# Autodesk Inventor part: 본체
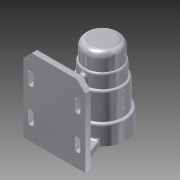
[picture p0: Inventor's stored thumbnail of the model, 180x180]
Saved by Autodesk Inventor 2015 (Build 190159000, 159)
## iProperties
Created: 2017-09
Part Number: 본체
Material: 알루미늄 6061
Document SubType Name: Modeling
Designer: Administrator
Density: 2.7 g/cm^3
Appearance: 알루미늄 - 평지
Mass: 695.321 g
Surface Area: 712.363 cm^2
Volume: 257.526 cm^3
Author: Administrator
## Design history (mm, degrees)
sketch "스케치1"
  geometry: L1 (-45, -56)-(45, -56); L2 (45, -56)-(45, 56); L3 (45, 56)-(-45, 56); L4 (-45, 56)-(-45, -56); L5 (-45, -56)-(45, 56); L6 (45, -56)-(-45, 56); 1 further point
  constraints: 12 end point, 2 midpoint, 2 parallel, 1 horizontal, 1 perpendicular
  dimensions: "d0" = 90 distance of L3.end L2.end; "d1" = 112 distance of L2.end L1.end
extrude "돌출1" new body sketch "스케치1" distance "d2" = 8; taper "d3" = 0 deg
sketch "스케치2"
  geometry: 1 further point
sketch "스케치3"
  geometry: L1 (0, -56)-(-8, -56) reference; L2 (-8, -56)-(-8, 56) reference; L3 (-8, 56)-(0, 56) reference; L4 (0, 56)-(0, -56) reference; L5 (62, -56)-(83, -56); L6 (83, -56)-(83, -41); L7 (83, -41)-(86, -41); L8 (86, -41)-(86, 13); L9 (86, 13)-(83, 13); L10 (83, 13)-(83, 25); L11 (83, 25)-(79, 25); L12 (79, 25)-(79, 43); L13 (79, 43)-(78, 43); L14 (78, 43)-(78, 47); L15 (78, 47)-(72.5, 47); L16 (72.5, 47)-(72.5, 50); L17 (72.5, 50)-(62, 50); L18 (83, -56)-(117.075, -56); L19 (62, 139.479)-(62, -56.834); L20 (62, 56)-(87, 56); L21 (87, 56)-(87, 31); L22 (87, 31)-(89, 31); L23 (89, 31)-(89, 11); L24 (89, 11)-(92, 11); L25 (92, 11)-(92, -28); L26 (92, -28)-(96, -28); L27 (83, -56)-(96, -56); L28 (96, -56)-(96, -28); 1 further point
  constraints: 48 end point, 18 perpendicular, 6 point on line, 2 horizontal, 2 vertical
  dimensions: "d4" = 70 distance from line of L2 L5.start; "d5" = 15 distance of L5.end L6.end; "d6" = 54 distance between parallel lines of L9 L7; "d7" = 12 distance between parallel lines of L11 L9; "d8" = 18 distance between parallel lines of L13 L11; "d9" = 4 distance of L13.end L14.end; "d10" = 3 distance of L15.end L16.end; "d11" = 42 diameter of L6 L19; "d12" = 21 diameter of L16 L19; "d13" = 32 diameter of L14 L19; "d14" = 34 diameter of L12 L19; "d15" = 42 diameter of L10 L19 (derived); "d16" = 48 diameter of L8 L19; "d17" = 112 distance between parallel lines of L20 L27; "d18" = 50 diameter of L21 L19; "d19" = 54 diameter of L23 L19; "d20" = 60 diameter of L25 L19; "d21" = 25 distance of L20.end L21.end; "d22" = 45 distance from line of L20 L24.end; "d23" = 84 distance between parallel lines of L26 L20; "d24" = 68 diameter of L28 L19
revolve "회전1" sketch "스케치3" stored, may be unused: angle "d25" = 90 deg
sketch "스케치4"
  geometry: L1 (0, -8)-(0, 0) reference; L2 (0, 0)-(90, 0) reference; L3 (90, 0)-(90, -8) reference; L4 (90, -8)-(0, -8) reference; L5 (90, 0)-(80, 0); L6 (0, 0)-(90, 0) reference; L7 (80, 0)-(66.9, 35.992); L8 (0, 0)-(10, 0); L9 (10, 0)-(23.1, 35.992); C1 r 21 at (45, 62) reference; A1 r 34 centre (45, 62) between (66.9, 35.992) and (23.1, 35.992) reference; 1 further point
  constraints: 8 end point, 2 point on circle, 2 point on line
  dimensions: "d26" = 10 distance of L2.end L5.end; "d27" = 110 deg angle of L5 L7; "d28" = 10 distance of L1.end L8.end
extrude "돌출2" join sketch "스케치4" distance "d30" = 8; taper "d31" = 0 deg
sketch "스케치5"
  geometry: L1 (-8, 56)-(0, 56) reference; L2 (0, 56)-(0, -48) reference; L3 (0, -48)-(28, -48) reference; L4 (28, -48)-(28, -28) reference; L5 (28, -28)-(32, -28) reference; L6 (32, -28)-(32, 11) reference; L7 (32, 11)-(35, 11) reference; L8 (35, 11)-(35, 31) reference; L9 (35, 31)-(37, 31) reference; L10 (37, 31)-(37, 56) reference; L11 (37, 56)-(87, 56) reference; L12 (87, 56)-(87, 31) reference; L13 (87, 31)-(89, 31) reference; L14 (89, 31)-(89, 11) reference; L15 (89, 11)-(92, 11) reference; L16 (92, 11)-(92, -28) reference; L17 (92, -28)-(96, -28) reference; L18 (96, -28)-(96, -56) reference; L19 (96, -56)-(83, -56) reference; L20 (83, -56)-(83, -41) reference; L21 (83, -41)-(86, -41) reference; L22 (86, -41)-(86, 13) reference; L23 (86, 13)-(83, 13) reference; L24 (83, 13)-(83, 25) reference; L25 (83, 25)-(79, 25) reference; L26 (79, 25)-(79, 43) reference; L27 (79, 43)-(78, 43) reference; L28 (78, 43)-(78, 47) reference; L29 (78, 47)-(72.5, 47) reference; L30 (72.5, 47)-(72.5, 50) reference; L31 (72.5, 50)-(51.5, 50) reference; L32 (51.5, 50)-(51.5, 47) reference; L33 (51.5, 47)-(46, 47) reference; L34 (46, 47)-(46, 43) reference; L35 (46, 43)-(45, 43) reference; L36 (45, 43)-(45, 25) reference; L37 (45, 25)-(41, 25) reference; L38 (41, 25)-(41, 13) reference; L39 (41, 13)-(38, 13) reference; L40 (38, 13)-(38, -41) reference; L41 (38, -41)-(41, -41) reference; L42 (41, -41)-(41, -56) reference; L43 (41, -56)-(-8, -56) reference; L44 (-8, -56)-(-8, 56) reference; L45 (0, 56)-(0, 34); L46 (0, -56)-(0, 56) reference; L47 (0, 34)-(38, 23.818); L48 (0, 34)-(39.34, 34); L49 (-8, 56)-(0, 56) reference; L50 (0, 56)-(0, -48) reference; L51 (0, -48)-(28, -48) reference; L52 (28, -48)-(28, -28) reference; L53 (28, -28)-(32, -28) reference; L54 (32, -28)-(32, 11) reference; L55 (32, 11)-(35, 11) reference; L56 (35, 11)-(35, 31) reference; L57 (35, 31)-(37, 31) reference; L58 (37, 31)-(37, 56) reference; L59 (37, 56)-(87, 56) reference; L60 (87, 56)-(87, 31) reference; L61 (87, 31)-(89, 31) reference; L62 (89, 31)-(89, 11) reference; L63 (89, 11)-(92, 11) reference; L64 (92, 11)-(92, -28) reference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; 1 further point
  constraints: 10 end point, 1 equal length, 1 horizontal, 1 midpoint, 1 point on line, 1 vertical
  dimensions: "d32" = 22 distance of L1.end L45.end; "d72" = 15 deg angle of L47 L48
  node "절단 모서리 투영3"
  node "절단 모서리 투영7"
  node "절단 모서리 투영8"
sketch "스케치6"
  geometry: L1 (-45, -56)-(-45, 56) reference; L2 (-45, 56)-(-35, 56) reference; L3 (-35, 48)-(-35, 56) reference; L4 (35, 48)-(-35, 48) reference; L5 (35, 56)-(35, 48) reference; L6 (35, 56)-(45, 56) reference; L7 (45, 56)-(45, -56) reference; L8 (45, -56)-(-45, -56) reference; L9 (-35, 56)-(35, 56) reference; L10 (-45, 56)-(-45, 34.95); L11 (-45, -56)-(-45, 56) reference; L12 (45, -56)-(-45, -56) reference; L13 (0, -56)-(-34, -56); L14 (-45, 22.956)-(-45, -17.044); L15 (-45, -17.044)-(-38, -17.044); L16 (-45, 56)-(-45, -56) reference; L17 (-34, 22.956)-(-34, -39.008); L18 (-30, -17.044)-(-30, -29.044); L19 (-38, -17.044)-(-38, -29.044); L20 (-30, -17.044)-(-30, -29.044); L21 (-38, -29.036)-(-37.974, -16.593); L22 (-45, 56)-(-45, 32); L23 (-45, 32)-(-34, 32); L24 (-34, 32)-(-34, 28.056); L25 (-34, 32)-(-34, 20); L26 (-30, 32)-(-30, 20); L27 (-38, 32)-(-38, 20); L28 (0, 28.056)-(-30, 28.056); L29 (-33.331, 28.056)-(-34, 28.056); C1 r 4 at (-34, -29.044); A1 r 4 centre (-34, -29.044) between (-38, -29.036) and (-30, -29.044); A2 r 4 centre (-34, -17.044) between (-30, -17.044) and (-38, -17.044); A3 r 4 centre (-34, 20) between (-38, 20) and (-30, 20); A4 r 4 centre (-34, 32) between (-34, 28) and (-33.331, 28.056); A5 r 4 centre (-34, 32) between (-30, 32) and (-38, 32); 2 further points
  constraints: 34 end point, 11 point on circle, 10 point on line, 6 centre point, 6 tangent, 4 coincident, 4 vertical, 3 horizontal, 2 perpendicular, 1 midpoint, 1 parallel, 3 other
  dimensions: "d36" = 34 distance of L13.start L13.end; "d44" = 40 distance of L14.start L14.end; "d49" = 12 distance of L18.start L18.end; "d50" = 12 distance of L15.end L19.end; "d87" = 24 distance of L1.end L22.end; "d88" = 34 distance of L28.start L24.end; "d90" = 12 distance of L25.start L25.end; "d91" = 8 diameter of A3
  node "절단 모서리 투영4"
chamfer "모따기1" distance "d53" = 12; stored, may be unused: second distance "d54" = 2, angle "d55" = 45 deg
sketch "스케치7" dims "d56" = 52
  geometry: L1 (0, 8)-(10, 8) reference; L2 (10, 8)-(23.1, 43.992) reference; L3 (66.9, 43.992)-(80, 8) reference; L4 (80, 8)-(90, 8) reference; L5 (90, 8)-(90, 0) reference; L6 (90, 0)-(0, 0) reference; L7 (0, 0)-(0, 8) reference; L8 (0, 8)-(10, 8) reference; L9 (10, 8)-(23.1, 43.992) reference; L10 (66.9, 43.992)-(80, 8) reference; L11 (80, 8)-(90, 8) reference; L12 (90, 8)-(90, 0) reference; L13 (90, 0)-(0, 0) reference; L14 (0, 0)-(0, 8) reference; C1 r 21 at (45, 70) reference; C2 r 21 at (45, 70) reference; A1 r 34 centre (45, 70) between (66.9, 43.992) and (23.1, 43.992) reference; A2 r 34 centre (45, 70) between (66.9, 43.992) and (23.1, 43.992) reference; 3 further points
  constraints: 1 coincident, 1 vertical alignment, 2 other
hole "구멍1" sketch "스케치7" at (45, 96) diameter "d57" = 3.242; stored, may be unused: countersink angle "d61" = 90 deg, drill point angle "d63" = 118 deg; dims "d58" = 8, "d59" = 4, "d60" = 2, "d62" = 11.8
fillet "모깎기3" dims "d69" = 3
fillet "모깎기4" dims "d70" = 0.3
extrude "돌출6" join sketch "스케치5" stored distance "d73" = 8; taper "d74" = 0 deg
fillet "모깎기5" dims "d75" = 3
fillet "모깎기6" dims "d76" = 3
fillet "모깎기7" dims "d77" = 9
fillet "모깎기8" dims "d78" = 3
node "작업 평면1"
node "작업 평면2"
sketch "스케치8"
  geometry: L1 (-70, -47.5)-(-70, 52.5) reference; L2 (-24.711, -47.5)-(34, -47.5) reference; 2 further points
  constraints: 1 other
  dimensions: "d80" = 70 distance from line of L1 point (0, 0.5); "d81" = 48 distance from line of L2 point (0, 0.5)
feature "엠보싱1" sketch "스케치8" dims "d0" = 90, "d1" = 112, "d4" = 70, "d5" = 15, "d6" = 54, "d7" = 12, "d8" = 18, "d9" = 4, "d10" = 3, "d11" = 42, "d12" = 21, "d13" = 32, "d14" = 34, "d15" = 42 (derived), "d16" = 48, "d17" = 112, "d18" = 50, "d19" = 54, "d20" = 60, "d21" = 25, "d22" = 45, "d23" = 84, "d24" = 68, "d82" = 0.5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
extrude "돌출7" cut sketch "스케치6" distance "d92" = 8; taper "d93" = 0 deg
node "솔리드1"
pattern_circular "원형 패턴1" dims angle "d65" = 360 deg
mirror "대칭2"
node "절단 모서리 투영1"
node "절단 모서리 투영2"
node "절단 모서리 투영5"
node "절단 모서리 투영6"
other parameters: "d29" = 110 deg, "d79" = 92.75, "d89" = 8
